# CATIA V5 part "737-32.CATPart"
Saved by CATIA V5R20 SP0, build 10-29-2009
Part number: 737-32
Definition: NONE
Nomenclature: 737-32
Source: Unknown
Description: 737-32
Bounding box of the stored display mesh (mm): x -36 to 28, y -35.911 to 35.911, z -47 to 25
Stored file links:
  C:\Users\Utente\Desktop\IO LAVORO\3D X SITO CF\X SITO\737\737-32.CATPart
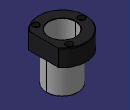
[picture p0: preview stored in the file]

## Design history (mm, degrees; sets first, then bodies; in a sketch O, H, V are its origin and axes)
Body1 "737-32" (main body)
  Solid1: solid without history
